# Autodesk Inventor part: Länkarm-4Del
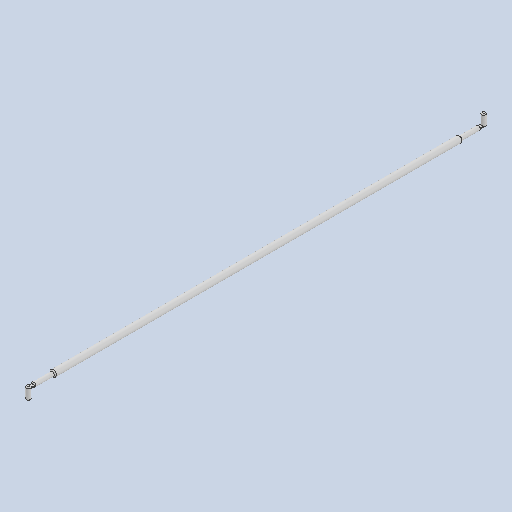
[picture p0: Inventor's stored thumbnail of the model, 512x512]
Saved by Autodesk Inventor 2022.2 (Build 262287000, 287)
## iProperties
Created: 2022-03
Part Number: Länkarm-4Del
Material: Generic
Document SubType Name: Modeling
Designer: cl
Density: 1 g/cm^3
Appearance: Default
Author: cl
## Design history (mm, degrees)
sketch "Sketch1"
  geometry: L1 (0, 0)-(0, -2066.69); L2 (0, 0)-(-10, 0); L3 (-10, 0)-(-10, -90); L4 (-10, -90)-(-15, -90); L5 (-15, -90)-(-15, -1976.69); L6 (0, -2066.69)-(-10, -2066.69); L7 (-10, -2066.69)-(-10, -1976.69); L8 (-10, -1976.69)-(-15, -1976.69); 1 further point
  constraints: 16 end point, 5 perpendicular, 2 horizontal, 1 midpoint, 1 vertical
  dimensions: "d0" = 2066.69 distance of L1.start L1.end (computed from BladBredd); "d1" = 20 diameter of L3 L1; "d2" = 5 distance between parallel lines of L3 L5; "d3" = 90 distance of L2.end L3.end; "d4" = 20 diameter of L7 L1; "d5" = 90 vertical distance of point (-5, -2066.69) L5.end
revolve "Revolution1" sketch "Sketch1" stored, may be unused: angle "d6" = 90 deg
fillet "Fillet1" dims "d7" = 5
workplane "Work Plane1"
sketch "Sketch2"
  geometry: L1 (10, 0)-(-10, 0) reference; L2 (7.5, 0)-(-7.5, 0); L3 (-7.5, 0)-(-7.5, 20); L4 (-7.5, 20)-(7.5, 20); L5 (7.5, 20)-(7.5, 0); L6 (10, -90)-(10, 0) reference; L7 (10, -2066.69)-(-10, -2066.69) reference; L8 (7.5, -2066.69)-(-7.5, -2066.69); L9 (-7.5, -2066.69)-(-7.5, -2086.69); L10 (-7.5, -2086.69)-(7.5, -2086.69); L11 (7.5, -2086.69)-(7.5, -2066.69); 3 further points
  constraints: 16 end point, 4 parallel, 2 horizontal, 2 perpendicular, 2 point on line, 1 collinear
  dimensions: "d9" = 2.5 distance between parallel lines of L5 L6; "d10" = 15 distance of L3.end L4.end; "d11" = 20 distance of L2.end L3.end; "d12" = 20 distance of L8.end L9.end; "d13" = 15 distance of L9.end L10.end
extrude "Extrusion1" join sketch "Sketch2" distance "d14" = 4; taper "d15" = 0 deg
sketch "Sketch3"
  geometry: L1 (7.5, 20)-(-7.5, 20) reference; L2 (-7.5, -2086.69)-(7.5, -2086.69) reference; C1 r 10 at (0, 20); C2 r 10 at (0, -2086.69); 1 further point
  constraints: 2 centre point, 2 midpoint
  dimensions: "d16" = 20 diameter of C1; "d17" = 20 diameter of C2
extrude "Extrusion2" join sketch "Sketch3" distance "d18" = 8; taper "d20" = 0 deg; dims "d19" = 48, "d21" = 0
extrude "Extrusion3" join sketch "Sketch3" distance "d22" = 50; taper "d24" = 0 deg; dims "d23" = 6, "d25" = 0
fillet "Fillet2" dims "d26" = 5
body "Solid1"
other parameters: "BladBredd" = 987.5, "Fönsterhöjd" = 862, "Blad2" = 1012.5, "Blad3" = 0, "Blad4" = 0, "Blad5" = 1012.5, "Blad6" = 2025, "MGJ12Djup" = 0, "MGJ12Bredd" = 0, "MGJ2Djup" = 0, "MGJ2Bredd" = 5012.5, "MGJ56Djup" = 0, "MGJ56Bredd" = 0, "MGJ23Djup" = 48, "MGJ45Djup" = 48, "GarageRegel5" = 0, "GarageRegel6" = 0, "Styrrulle2Djup" = 0, "FönsterhöjdStyrning" = 862, "FönsterKarm" = 54, "AndraGlasraden" = 0, "BrösthöjdStyrning2" = 0.0001, "InfälldGångDörr" = 0, "Infälldstyr" = 1030.33333, "EnDelGångDörr" = 0, "VinkelJärnStyrSkena" = 1456.25, "d8" = -2
